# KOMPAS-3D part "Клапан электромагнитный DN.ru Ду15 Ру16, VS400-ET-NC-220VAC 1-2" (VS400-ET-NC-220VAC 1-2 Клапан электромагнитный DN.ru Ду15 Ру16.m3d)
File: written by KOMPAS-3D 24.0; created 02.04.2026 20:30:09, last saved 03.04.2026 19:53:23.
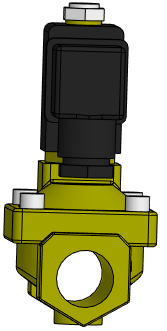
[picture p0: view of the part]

Document properties: Автор: artio; Полное имя файла: C:\Users\artio\OneDrive\Рабочий стол\Клапан электромагнитный DN.ru\VS400-ET-NC-220VAC 1-2 Клапан электромагнитный DN.ru Ду15 Ру16.m3d

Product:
- Body: Тело 1  | qty 1
    Масса: 1.030062
- Part/product: Клапан электромагнитный DN.ru Ду15 Ру16  | designation VS400-ET-NC-220VAC 1-2
    Масса: 0.759
    Раздел спецификации: Прочие изделия
    Примечание: D130-04691
    additional columns: ef56311e-7521-43dc-8291-0e6108b3d81d; VS400-ET-NC-220VAC 1-2; artio; c; Шероховатость не задана; Да

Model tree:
1. Операция без истории:1

Expressions: VS400-ET-NC-220VAC 1-2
